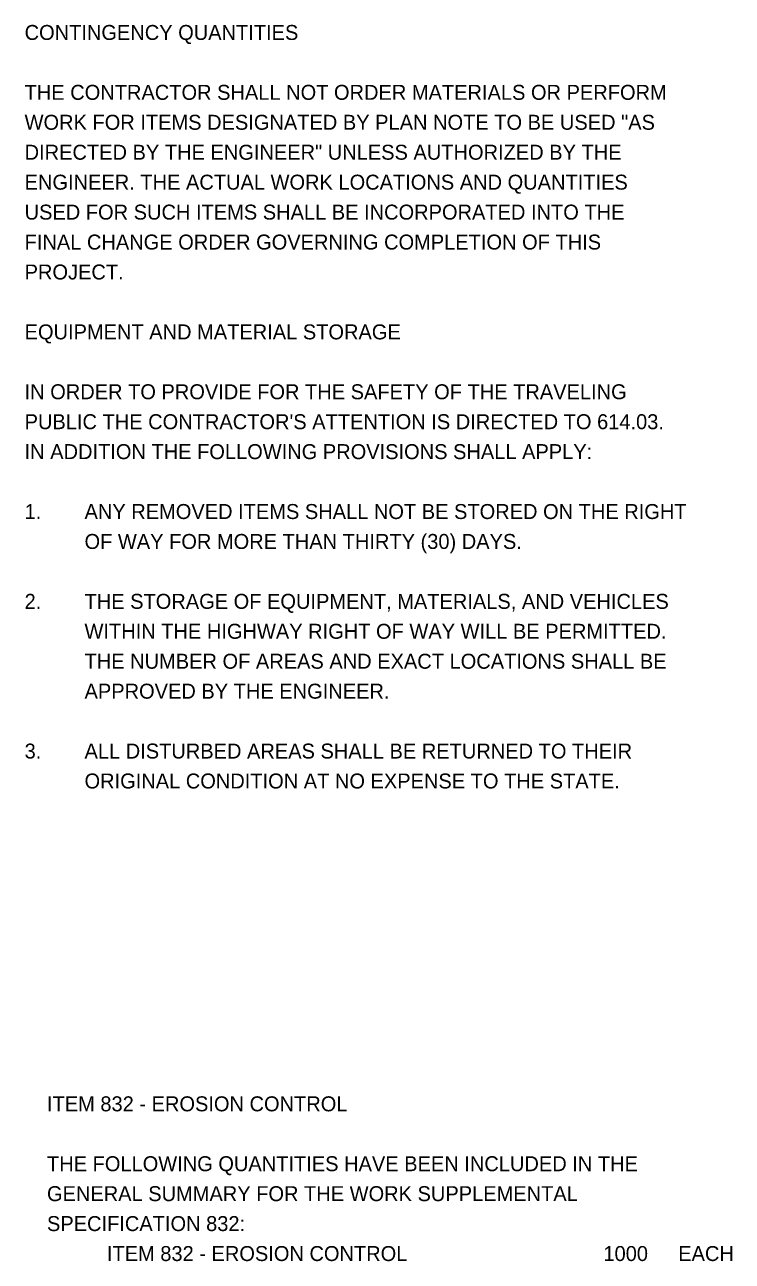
# Model space of a CAD drawing. Extents: x 0 to 34, y -14.6 to 28.2.
# Drawn here: x 18.05 to 24.67, y -14.65 to -3.08 of the extents above; entities that cross this region are included whole.
import ezdxf

# ---------------------------------------------------------------- set-up
doc = ezdxf.new("R2010")
doc.units = 0
doc.layers.add('SH_Text', color=7, linetype='Continuous')

msp = doc.modelspace()

# ---------------------------------------------------------------- texts
at = {"layer": 'SH_Text'}
for s, p in [('CONTINGENCY QUANTITIES', (18.053, -3.225)), ('THE CONTRACTOR SHALL NOT ORDER MATERIALS OR PERFORM', (18.053, -3.785)), ('WORK FOR ITEMS DESIGNATED BY PLAN NOTE TO BE USED "AS', (18.053, -4.065)), ('DIRECTED BY THE ENGINEER" UNLESS AUTHORIZED BY THE', (18.053, -4.345)), ('ENGINEER. THE ACTUAL WORK LOCATIONS AND QUANTITIES', (18.053, -4.625)), ('USED FOR SUCH ITEMS SHALL BE INCORPORATED INTO THE', (18.053, -4.905)), ('FINAL CHANGE ORDER GOVERNING COMPLETION OF THIS', (18.053, -5.185)), ('PROJECT.', (18.053, -5.465)), ('EQUIPMENT AND MATERIAL STORAGE', (18.053, -6.025)), ('IN ORDER TO PROVIDE FOR THE SAFETY OF THE TRAVELING ', (18.053, -6.585)), ("PUBLIC THE CONTRACTOR'S ATTENTION IS DIRECTED TO 614.03.", (18.053, -6.865)), ('IN ADDITION THE FOLLOWING PROVISIONS SHALL APPLY:', (18.053, -7.145)), ('1.', (18.053, -7.705)), ('ANY REMOVED ITEMS SHALL NOT BE STORED ON THE RIGHT', (18.613, -7.705)), ('OF WAY FOR MORE THAN THIRTY (30) DAYS.', (18.613, -7.985)), ('2.', (18.053, -8.545)), ('THE STORAGE OF EQUIPMENT, MATERIALS, AND VEHICLES', (18.613, -8.545)), ('WITHIN THE HIGHWAY RIGHT OF WAY WILL BE PERMITTED.', (18.613, -8.825)), ('THE NUMBER OF AREAS AND EXACT LOCATIONS SHALL BE', (18.613, -9.105)), ('APPROVED BY THE ENGINEER.', (18.613, -9.385)), ('3.', (18.053, -9.945)), ('ALL DISTURBED AREAS SHALL BE RETURNED TO THEIR ', (18.613, -9.945)), ('ORIGINAL CONDITION AT NO EXPENSE TO THE STATE.', (18.613, -10.225)), ('ITEM 832 - EROSION CONTROL', (18.262, -13.244)), ('THE FOLLOWING QUANTITIES HAVE BEEN INCLUDED IN THE ', (18.262, -13.804)), ('GENERAL SUMMARY FOR THE WORK SUPPLEMENTAL ', (18.262, -14.084)), ('SPECIFICATION 832:', (18.262, -14.364)), ('ITEM 832 - EROSION CONTROL ', (18.822, -14.644)), (' 1000 ', (23.411, -14.644)), ('    EACH', (23.954, -14.644))]:
    msp.add_text(s, height=0.14, dxfattribs=at).set_placement(p)

doc.saveas('drawing.dxf')
